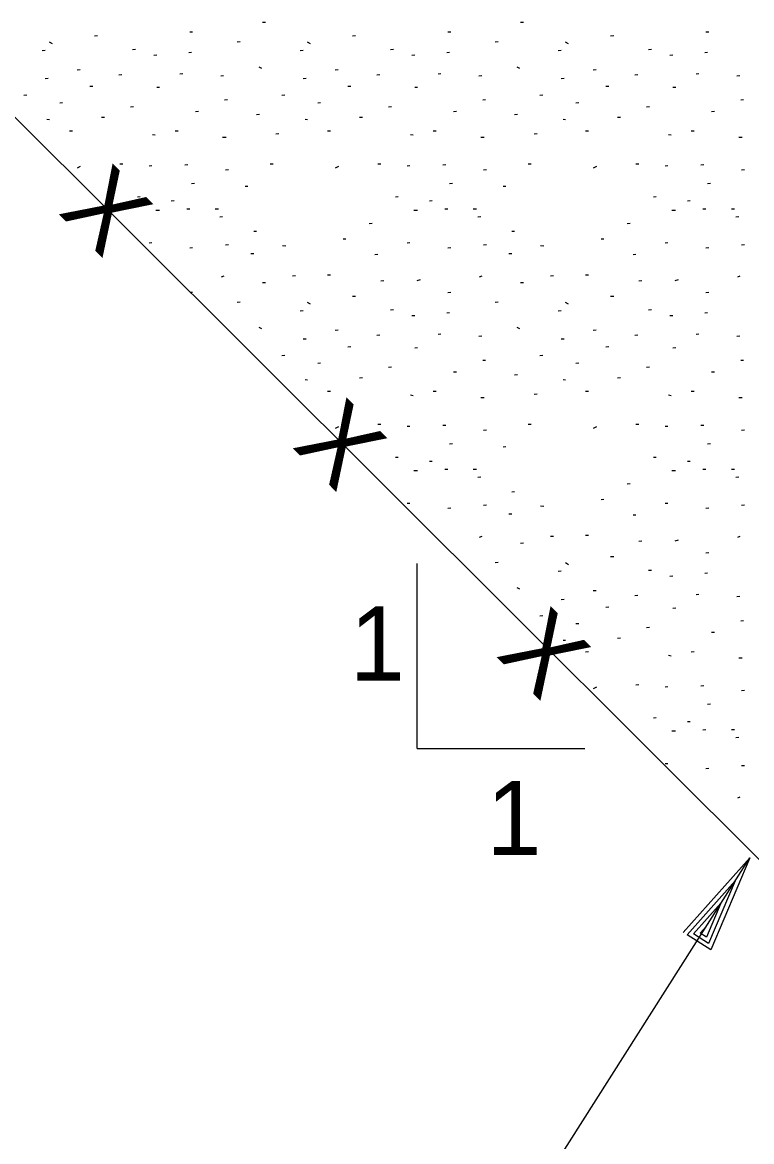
# Model space of a CAD drawing. Extents: x 0 to 320, y -4 to 473.
# Drawn here: x 20.664 to 22.043, y 13.7 to 15.816 of the extents above; entities that cross this region are included whole.
import ezdxf

# ---------------------------------------------------------------- set-up
doc = ezdxf.new("R2010")
doc.units = 0
for name, color, linetype in [('Level 3', 7, 'Continuous'), ('Level 44', 7, 'Continuous'), ('Level 50', 7, 'Continuous')]:
    doc.layers.add(name, color=color, linetype=linetype)

msp = doc.modelspace()

# ---------------------------------------------------------------- linework, layer by layer
at = {"layer": 'Level 3'}
for p, q in [((21.1232, 15.8163), (21.1177, 15.8159)), ((21.6113, 15.8163), (21.6058, 15.8159)), ((22.4474, 13.8444), (20.4869, 15.7986)), ((20.8058, 15.7907), (20.8002, 15.7903)), ((20.9857, 15.7981), (20.9802, 15.7976)), ((21.2939, 15.7907), (21.2883, 15.7903)), ((21.4738, 15.7981), (21.4683, 15.7976)), ((21.7821, 15.7907), (21.7764, 15.7903)), ((21.9619, 15.7981), (21.9564, 15.7976)), ((20.7206, 15.7757), (20.7149, 15.7791)), ((21.0756, 15.7797), (21.0701, 15.7792)), ((21.2087, 15.7757), (21.2031, 15.7791)), ((21.5637, 15.7797), (21.5582, 15.7792)), ((21.6968, 15.7757), (21.6912, 15.7791)), ((20.7067, 15.7632), (20.7012, 15.7627)), ((20.8773, 15.7649), (20.8718, 15.7644)), ((20.9177, 15.7541), (20.9122, 15.7536)), ((20.9837, 15.7594), (20.9782, 15.7589)), ((21.1948, 15.7632), (21.1893, 15.7627)), ((21.3654, 15.7649), (21.3599, 15.7644)), ((21.4058, 15.7541), (21.4003, 15.7536)), ((21.4718, 15.7594), (21.4663, 15.7589)), ((21.6829, 15.7632), (21.6774, 15.7627)), ((21.8536, 15.7649), (21.8481, 15.7644)), ((21.8939, 15.7541), (21.8884, 15.7536)), ((21.9599, 15.7594), (21.9544, 15.7589)), ((20.7728, 15.7264), (20.7673, 15.7261)), ((21.1167, 15.7293), (21.1114, 15.7318)), ((21.2609, 15.7264), (21.2554, 15.7261)), ((21.6048, 15.7293), (21.5996, 15.7318)), ((21.7491, 15.7264), (21.7436, 15.7261)), ((20.7122, 15.7099), (20.7067, 15.7094)), ((20.8517, 15.7172), (20.8462, 15.7168)), ((20.9672, 15.7192), (20.9617, 15.7187)), ((21.0443, 15.7154), (21.0387, 15.7149)), ((21.2003, 15.7099), (21.1948, 15.7094)), ((21.3398, 15.7172), (21.3343, 15.7168)), ((21.4553, 15.7192), (21.4498, 15.7187)), ((21.5324, 15.7154), (21.5268, 15.7149)), ((21.6884, 15.7099), (21.6829, 15.7094)), ((21.8279, 15.7172), (21.8224, 15.7168)), ((21.9434, 15.7192), (21.9379, 15.7187)), ((22.0206, 15.7154), (22.0149, 15.7149)), ((20.7967, 15.6953), (20.7912, 15.6948)), ((20.9232, 15.6934), (20.9177, 15.6929)), ((21.2848, 15.6953), (21.2793, 15.6948)), ((21.4113, 15.6934), (21.4058, 15.6929)), ((21.7729, 15.6953), (21.7674, 15.6948)), ((21.8994, 15.6934), (21.8939, 15.6929)), ((20.6718, 15.6788), (20.6663, 15.6783)), ((20.7397, 15.6641), (20.7342, 15.6636)), ((21.0517, 15.6696), (21.0462, 15.6691)), ((21.1599, 15.6788), (21.1544, 15.6783)), ((21.2278, 15.6641), (21.2223, 15.6636)), ((21.5398, 15.6696), (21.5343, 15.6691)), ((21.6481, 15.6788), (21.6426, 15.6783)), ((21.7159, 15.6641), (21.7104, 15.6636)), ((22.0279, 15.6696), (22.0224, 15.6691)), ((20.8737, 15.6567), (20.8682, 15.6563)), ((20.9966, 15.6476), (20.9911, 15.6472)), ((21.1122, 15.6421), (21.1067, 15.6417)), ((21.3618, 15.6567), (21.3563, 15.6563)), ((21.4847, 15.6476), (21.4792, 15.6472)), ((21.6003, 15.6421), (21.5948, 15.6417)), ((21.8499, 15.6567), (21.8444, 15.6563)), ((21.9728, 15.6476), (21.9673, 15.6472)), ((20.7149, 15.6321), (20.7101, 15.6326)), ((20.8187, 15.6366), (20.8132, 15.6362)), ((21.2031, 15.6321), (21.1982, 15.6326)), ((21.3068, 15.6366), (21.3013, 15.6362)), ((21.6912, 15.6321), (21.6863, 15.6326)), ((21.7949, 15.6366), (21.7894, 15.6362)), ((20.7581, 15.6109), (20.7526, 15.6104)), ((20.9148, 15.6028), (20.9097, 15.6037)), ((20.9581, 15.6109), (20.9526, 15.6104)), ((21.0492, 15.5987), (21.0424, 15.5987)), ((21.1489, 15.6054), (21.1433, 15.6049)), ((21.2462, 15.6109), (21.2407, 15.6104)), ((21.4029, 15.6028), (21.3978, 15.6037)), ((21.4462, 15.6109), (21.4407, 15.6104)), ((21.5373, 15.5987), (21.5306, 15.5987)), ((21.6371, 15.6054), (21.6314, 15.6049)), ((21.7343, 15.6109), (21.7288, 15.6104)), ((21.8911, 15.6028), (21.8859, 15.6037)), ((21.9343, 15.6109), (21.9288, 15.6104)), ((22.0254, 15.5987), (22.0187, 15.5987)), ((20.7732, 15.5439), (20.7673, 15.5409)), ((20.8534, 15.5484), (20.8479, 15.5481)), ((20.9086, 15.5448), (20.9031, 15.5443)), ((20.9764, 15.5467), (20.9709, 15.5462)), ((21.0534, 15.5374), (21.0479, 15.5371)), ((21.1378, 15.5484), (21.1323, 15.5481)), ((21.2613, 15.5439), (21.2554, 15.5409)), ((21.3416, 15.5484), (21.3361, 15.5481)), ((21.3967, 15.5448), (21.3912, 15.5443)), ((21.4646, 15.5467), (21.4591, 15.5462)), ((21.5416, 15.5374), (21.5361, 15.5371)), ((21.6259, 15.5484), (21.6204, 15.5481)), ((21.7494, 15.5439), (21.7436, 15.5409)), ((21.8297, 15.5484), (21.8242, 15.5481)), ((21.8848, 15.5448), (21.8793, 15.5443)), ((21.9527, 15.5467), (21.9472, 15.5462)), ((22.0297, 15.5374), (22.0242, 15.5371)), ((20.9892, 15.5118), (20.9837, 15.5113)), ((21.0902, 15.5063), (21.0847, 15.5058)), ((21.4773, 15.5118), (21.4718, 15.5113)), ((21.5783, 15.5063), (21.5728, 15.5058)), ((21.9654, 15.5118), (21.9599, 15.5113)), ((20.8866, 15.4862), (20.8811, 15.4857)), ((20.9508, 15.4787), (20.9453, 15.4783)), ((21.3747, 15.4862), (21.3692, 15.4857)), ((21.4389, 15.4787), (21.4334, 15.4783)), ((21.8628, 15.4862), (21.8573, 15.4857)), ((21.9271, 15.4787), (21.9216, 15.4783)), ((20.9228, 15.4606), (20.9161, 15.4606)), ((20.9802, 15.4633), (20.9746, 15.4629)), ((21.0347, 15.4633), (21.0284, 15.4633)), ((21.4109, 15.4606), (21.4042, 15.4606)), ((21.4683, 15.4633), (21.4627, 15.4629)), ((21.5228, 15.4633), (21.5166, 15.4633)), ((21.8991, 15.4606), (21.8923, 15.4606)), ((21.9564, 15.4633), (21.9508, 15.4629)), ((22.0109, 15.4633), (22.0047, 15.4633)), ((21.0424, 15.4487), (21.0369, 15.4483)), ((21.3252, 15.4359), (21.3197, 15.4354)), ((21.5306, 15.4487), (21.5251, 15.4483)), ((21.8133, 15.4359), (21.8078, 15.4354)), ((22.0187, 15.4487), (22.0132, 15.4483)), ((21.1067, 15.4212), (21.1012, 15.4207)), ((21.5948, 15.4212), (21.5893, 15.4207)), ((20.9086, 15.3992), (20.9031, 15.3988)), ((20.9857, 15.3901), (20.9802, 15.3896)), ((21.0534, 15.3956), (21.0479, 15.3951)), ((21.1621, 15.3931), (21.1556, 15.3941)), ((21.2756, 15.4066), (21.2701, 15.4061)), ((21.3967, 15.3992), (21.3912, 15.3988)), ((21.4738, 15.3901), (21.4683, 15.3896)), ((21.5416, 15.3956), (21.5361, 15.3951)), ((21.6502, 15.3931), (21.6437, 15.3941)), ((21.7637, 15.4066), (21.7582, 15.4061)), ((21.8848, 15.3992), (21.8793, 15.3988)), ((21.9619, 15.3901), (21.9564, 15.3896)), ((22.0297, 15.3956), (22.0242, 15.3951)), ((21.1012, 15.3789), (21.0957, 15.3786)), ((21.3361, 15.3772), (21.3306, 15.3767)), ((21.5893, 15.3789), (21.5838, 15.3786)), ((21.8242, 15.3772), (21.8187, 15.3767)), ((21.0446, 15.3363), (21.0398, 15.3344)), ((21.1232, 15.3239), (21.1177, 15.3236)), ((21.1801, 15.3368), (21.1746, 15.3363)), ((21.2462, 15.3386), (21.2407, 15.3382)), ((21.3471, 15.3277), (21.3416, 15.3272)), ((21.4163, 15.3296), (21.4096, 15.3277)), ((21.5327, 15.3363), (21.5279, 15.3344)), ((21.6113, 15.3239), (21.6058, 15.3236)), ((21.6682, 15.3368), (21.6627, 15.3363)), ((21.7343, 15.3386), (21.7288, 15.3382)), ((21.8352, 15.3277), (21.8297, 15.3272)), ((21.9044, 15.3296), (21.8977, 15.3277)), ((22.0208, 15.3363), (22.0161, 15.3344)), ((20.9857, 15.3057), (20.9818, 15.3053)), ((21.4738, 15.3057), (21.4683, 15.3052)), ((21.9619, 15.3057), (21.9564, 15.3052)), ((21.0756, 15.2873), (21.0701, 15.2868)), ((21.2087, 15.2833), (21.2031, 15.2867)), ((21.2939, 15.2983), (21.2883, 15.2979)), ((21.5637, 15.2873), (21.5582, 15.2868)), ((21.6968, 15.2833), (21.6912, 15.2867)), ((21.7821, 15.2983), (21.7764, 15.2979)), ((21.1948, 15.2708), (21.1893, 15.2703)), ((21.3654, 15.2726), (21.3599, 15.2721)), ((21.4058, 15.2617), (21.4003, 15.2612)), ((21.4718, 15.2671), (21.4663, 15.2666)), ((21.6829, 15.2708), (21.6774, 15.2703)), ((21.8536, 15.2726), (21.8481, 15.2721)), ((21.8939, 15.2617), (21.8884, 15.2612)), ((21.9599, 15.2671), (21.9544, 15.2666)), ((21.1167, 15.2369), (21.1114, 15.2394)), ((21.6048, 15.2369), (21.5996, 15.2394)), ((21.2003, 15.2176), (21.1948, 15.2171)), ((21.2609, 15.2341), (21.2554, 15.2337)), ((21.3398, 15.2248), (21.3343, 15.2244)), ((21.4553, 15.2268), (21.4498, 15.2263)), ((21.5324, 15.2231), (21.5268, 15.2226)), ((21.6884, 15.2176), (21.6829, 15.2171)), ((21.7491, 15.2341), (21.7436, 15.2337)), ((21.8279, 15.2248), (21.8224, 15.2244)), ((21.9434, 15.2268), (21.9379, 15.2263)), ((22.0206, 15.2231), (22.0149, 15.2226)), ((21.2848, 15.2029), (21.2793, 15.2024)), ((21.4113, 15.2011), (21.4058, 15.2006)), ((21.7729, 15.2029), (21.7674, 15.2024)), ((21.8994, 15.2011), (21.8939, 15.2006)), ((21.1599, 15.1864), (21.1544, 15.1859)), ((21.5398, 15.1772), (21.5343, 15.1767)), ((21.6481, 15.1864), (21.6426, 15.1859)), ((22.0279, 15.1772), (22.0224, 15.1767)), ((21.2278, 15.1717), (21.2223, 15.1712)), ((21.3618, 15.1643), (21.3563, 15.1639)), ((21.4847, 15.1552), (21.4792, 15.1548)), ((21.7159, 15.1717), (21.7104, 15.1712)), ((21.8499, 15.1643), (21.8444, 15.1639)), ((21.9728, 15.1552), (21.9673, 15.1548)), ((21.2031, 15.1397), (21.1982, 15.1402)), ((21.3068, 15.1442), (21.3013, 15.1438)), ((21.6003, 15.1497), (21.5948, 15.1493)), ((21.6912, 15.1397), (21.6863, 15.1402)), ((21.7949, 15.1442), (21.7894, 15.1438)), ((21.2462, 15.1186), (21.2407, 15.1181)), ((21.4029, 15.1104), (21.3978, 15.1113)), ((21.4462, 15.1186), (21.4407, 15.1181)), ((21.6371, 15.1131), (21.6314, 15.1126)), ((21.7343, 15.1186), (21.7288, 15.1181)), ((21.8911, 15.1104), (21.8859, 15.1113)), ((21.9343, 15.1186), (21.9288, 15.1181)), ((21.5373, 15.1063), (21.5306, 15.1063)), ((22.0254, 15.1063), (22.0187, 15.1063)), ((21.2613, 15.0516), (21.2554, 15.0486)), ((21.3416, 15.0561), (21.3361, 15.0557)), ((21.3967, 15.0524), (21.3912, 15.0519)), ((21.4646, 15.0543), (21.4591, 15.0538)), ((21.6259, 15.0561), (21.6204, 15.0557)), ((21.7494, 15.0516), (21.7436, 15.0486)), ((21.8297, 15.0561), (21.8242, 15.0557)), ((21.8848, 15.0524), (21.8793, 15.0519)), ((21.9527, 15.0543), (21.9472, 15.0538)), ((21.5416, 15.0451), (21.5361, 15.0447)), ((22.0297, 15.0451), (22.0242, 15.0447)), ((21.4773, 15.0194), (21.4718, 15.0189)), ((21.5783, 15.0139), (21.5728, 15.0134)), ((21.9654, 15.0194), (21.9599, 15.0189)), ((21.3747, 14.9938), (21.3692, 14.9933)), ((21.4389, 14.9863), (21.4334, 14.9859)), ((21.8628, 14.9938), (21.8573, 14.9933)), ((21.9271, 14.9863), (21.9216, 14.9859)), ((21.4109, 14.9682), (21.4042, 14.9682)), ((21.4683, 14.9709), (21.4627, 14.9706)), ((21.5228, 14.9709), (21.5166, 14.9709)), ((21.8991, 14.9682), (21.8923, 14.9682)), ((21.9564, 14.9709), (21.9508, 14.9706)), ((22.0109, 14.9709), (22.0047, 14.9709)), ((21.5306, 14.9563), (21.5251, 14.9559)), ((21.8133, 14.9436), (21.8078, 14.9431)), ((22.0187, 14.9563), (22.0132, 14.9559)), ((21.5948, 14.9288), (21.5893, 14.9283)), ((21.3967, 14.9068), (21.3912, 14.9064)), ((21.5416, 14.9032), (21.5361, 14.9027)), ((21.6502, 14.9007), (21.6437, 14.9017)), ((21.7637, 14.9142), (21.7582, 14.9137)), ((21.8848, 14.9068), (21.8793, 14.9064)), ((22.0297, 14.9032), (22.0242, 14.9027)), ((21.4738, 14.8977), (21.4683, 14.8972)), ((21.5893, 14.8866), (21.5838, 14.8862)), ((21.8242, 14.8848), (21.8187, 14.8843)), ((21.9619, 14.8977), (21.9564, 14.8972)), ((21.5327, 14.8439), (21.5279, 14.8421)), ((21.6682, 14.8444), (21.6627, 14.8439)), ((21.7343, 14.8462), (21.7288, 14.8458)), ((21.9044, 14.8372), (21.8977, 14.8353)), ((22.0208, 14.8439), (22.0161, 14.8421)), ((21.6113, 14.8316), (21.6058, 14.8312)), ((21.8352, 14.8353), (21.8297, 14.8348)), ((21.4104, 14.4436), (21.4104, 14.7931)), ((21.5637, 14.7949), (21.5582, 14.7944)), ((21.6968, 14.7909), (21.6912, 14.7943)), ((21.7821, 14.8059), (21.7764, 14.8056)), ((21.9619, 14.8133), (21.9564, 14.8128)), ((21.6829, 14.7784), (21.6774, 14.7779)), ((21.8536, 14.7802), (21.8481, 14.7797)), ((21.9599, 14.7747), (21.9544, 14.7742)), ((21.8939, 14.7693), (21.8884, 14.7688)), ((21.6048, 14.7446), (21.5996, 14.7471)), ((21.7491, 14.7417), (21.7436, 14.7413)), ((21.8279, 14.7324), (21.8224, 14.7321)), ((21.9434, 14.7344), (21.9379, 14.7339)), ((22.0206, 14.7307), (22.0149, 14.7302)), ((21.6884, 14.7252), (21.6829, 14.7247)), ((21.7729, 14.7106), (21.7674, 14.7101)), ((21.8994, 14.7087), (21.8939, 14.7082)), ((21.6481, 14.6941), (21.6426, 14.6936)), ((21.7159, 14.6793), (21.7104, 14.6788)), ((21.8499, 14.6719), (21.8444, 14.6716)), ((22.0279, 14.6848), (22.0224, 14.6843)), ((21.6912, 14.6473), (21.6863, 14.6478)), ((21.7949, 14.6518), (21.7894, 14.6514)), ((21.9728, 14.6628), (21.9673, 14.6624)), ((21.7343, 14.6262), (21.7288, 14.6257)), ((21.9343, 14.6262), (21.9288, 14.6257)), ((21.8911, 14.6181), (21.8859, 14.6189)), ((22.0254, 14.6139), (22.0187, 14.6139)), ((21.8297, 14.5637), (21.8242, 14.5633)), ((21.9527, 14.5619), (21.9472, 14.5614)), ((21.7494, 14.5592), (21.7436, 14.5562)), ((21.8848, 14.5601), (21.8793, 14.5596)), ((22.0297, 14.5527), (22.0242, 14.5523)), ((21.9654, 14.5271), (21.9599, 14.5266)), ((21.8628, 14.5014), (21.8573, 14.5009)), ((21.8991, 14.4758), (21.8923, 14.4758)), ((21.9271, 14.4939), (21.9216, 14.4936)), ((21.9564, 14.4786), (21.9508, 14.4782)), ((22.0109, 14.4786), (22.0047, 14.4786)), ((22.0187, 14.4639), (22.0132, 14.4636)), ((21.4104, 14.4436), (21.7276, 14.4436)), ((21.8848, 14.4144), (21.8793, 14.4141)), ((21.9619, 14.4053), (21.9564, 14.4048)), ((22.0297, 14.4108), (22.0242, 14.4103)), ((22.0208, 14.3516), (22.0161, 14.3497))]:
    msp.add_line(p, q, dxfattribs=at)
msp.add_lwpolyline([(21.0289, 13.2421), (21.408, 13.2421), (22.0398, 14.2369)], dxfattribs=at)
at = {"layer": 'Level 50'}
for p, q in [((22.0398, 14.2369), (22.0398, 14.2369)), ((22.012, 14.193), (22.012, 14.193))]:
    msp.add_line(p, q, dxfattribs=at)
msp.add_lwpolyline([(21.9134, 14.0956), (22.0398, 14.2369), (21.9657, 14.0624), (21.921, 14.0908), (22.012, 14.193), (21.9616, 14.0745), (21.9329, 14.0927), (21.9851, 14.1508), (21.9574, 14.0866), (21.9456, 14.0941), (21.9573, 14.1069)], dxfattribs=at)

# ---------------------------------------------------------------- texts
at = {"layer": 'Level 3'}
for p in [(21.283, 14.5719), (21.5412, 14.242)]:
    msp.add_text('1', height=0.14, dxfattribs=at).set_placement(p)
at = {"layer": 'Level 44'}
for p in [(20.7296, 15.4564), (21.1719, 15.0139), (21.558, 14.6191)]:
    msp.add_text('X', height=0.14, rotation=315, dxfattribs=at).set_placement(p)

doc.saveas('drawing.dxf')
